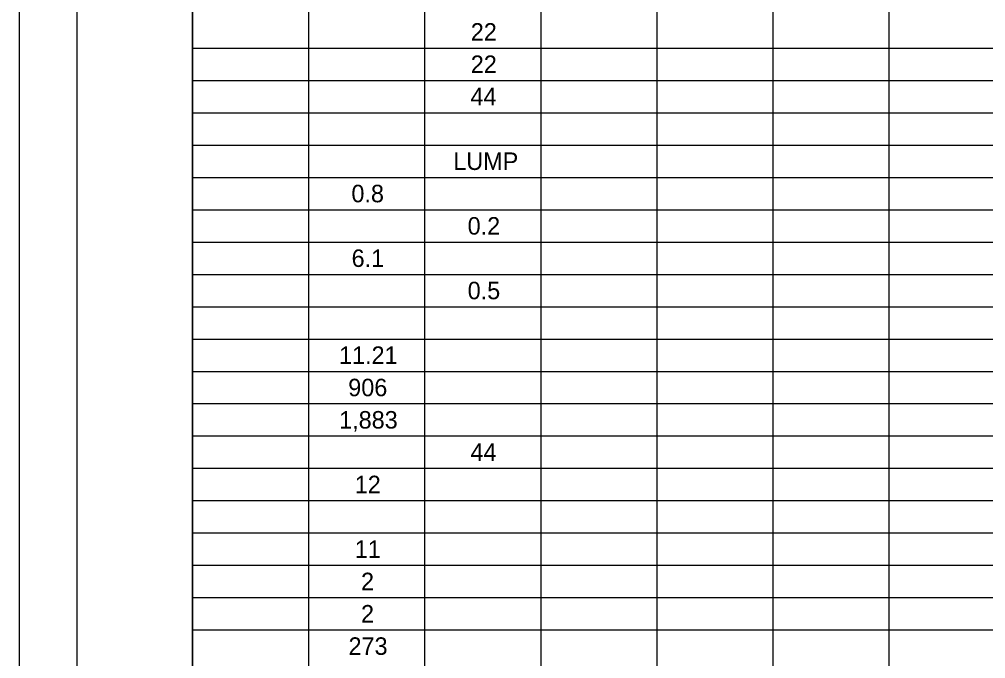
# Model space of a CAD drawing. Extents: x 45.7 to 120.9, y -0.1 to 21.9.
# Drawn here: x 86.86 to 95.22, y 10.8 to 16.34 of the extents above; entities that cross this region are included whole.
import ezdxf

# ---------------------------------------------------------------- set-up
doc = ezdxf.new("R2010")
doc.units = 0
for name, color, linetype in [('SH_Border', 7, 'Continuous'), ('SH_Cut_Line', 7, 'Continuous'), ('SH_Text', 7, 'Continuous')]:
    doc.layers.add(name, color=color, linetype=linetype)

msp = doc.modelspace()

# ---------------------------------------------------------------- linework, layer by layer
at = {"layer": 'SH_Border'}
for points in [[(87.3564, 21.4091), (88.3564, 21.4091), (88.3564, 0.4091), (87.3564, 0.4091)], [(88.3564, 21.4091), (120.3564, 21.4091), (120.3564, 0.4091), (88.3564, 0.4091)]]:
    msp.add_lwpolyline(points, close=True, dxfattribs=at)
at = {"layer": 'SH_Cut_Line'}
msp.add_lwpolyline([(86.8564, -0.0909), (120.8564, -0.0909), (120.8564, 21.9091), (86.8564, 21.9091)], close=True, dxfattribs=at)
at = {"layer": 'SH_Text'}
for p, q in [((88.3564, 21.4091), (88.3564, 0.4091)), ((89.3611, 20.8491), (89.3611, 0.4091)), ((90.3658, 20.8491), (90.3658, 0.4091)), ((91.3705, 20.8491), (91.3705, 0.4091)), ((92.3752, 20.8491), (92.3752, 0.4091)), ((93.3799, 20.8491), (93.3799, 0.4091)), ((94.3846, 20.8491), (94.3846, 0.4091)), ((88.3564, 16.0891), (118.8599, 16.0891)), ((88.3564, 15.8091), (118.8599, 15.8091)), ((88.3564, 15.5291), (118.8599, 15.5291)), ((88.3564, 15.2491), (118.8599, 15.2491)), ((88.3564, 14.9691), (118.8599, 14.9691)), ((88.3564, 14.6891), (118.8599, 14.6891)), ((88.3564, 14.4091), (118.8599, 14.4091)), ((88.3564, 14.1291), (118.8599, 14.1291)), ((88.3564, 13.8491), (118.8599, 13.8491)), ((88.3564, 13.5691), (118.8599, 13.5691)), ((88.3564, 13.2891), (118.8599, 13.2891)), ((88.3564, 13.0091), (118.8599, 13.0091)), ((88.3564, 12.7291), (118.8599, 12.7291)), ((88.3564, 12.4491), (118.8599, 12.4491)), ((88.3564, 12.1691), (118.8599, 12.1691)), ((88.3564, 11.8891), (118.8599, 11.8891)), ((88.3564, 11.6091), (118.8599, 11.6091)), ((88.3564, 11.3291), (118.8599, 11.3291)), ((88.3564, 11.0491), (118.8599, 11.0491))]:
    msp.add_line(p, q, dxfattribs=at)

# ---------------------------------------------------------------- texts
for s, height, p in [('22', 0.15153, (90.7653, 16.1534)), ('22', 0.15153, (90.7653, 15.8734)), ('44', 0.15153, (90.7624, 15.5934)), ('LUMP', 0.15153, (90.6138, 15.0334)), ('0.8', 0.15153, (89.7319, 14.7534)), ('0.2', 0.15153, (90.7381, 14.4734)), ('6.1', 0.15153, (89.7333, 14.1934)), ('0.5', 0.15153, (90.7384, 13.9134)), ('11.21', 0.15153, (89.6244, 13.3534)), ('906', 0.15153, (89.7044, 13.0734)), ('1,883', 0.15153, (89.6255, 12.7934)), ('44', 0.15153, (90.7624, 12.5134)), ('12', 0.15153, (89.7606, 12.2334)), ('11', 0.15153, (89.7604, 11.6734)), ('2', 0.1515, (89.815, 11.3934)), ('2', 0.1515, (89.815, 11.1134)), ('273', 0.15153, (89.7067, 10.8334))]:
    msp.add_text(s, height=height, dxfattribs=at).set_placement(p)

doc.saveas('drawing.dxf')
